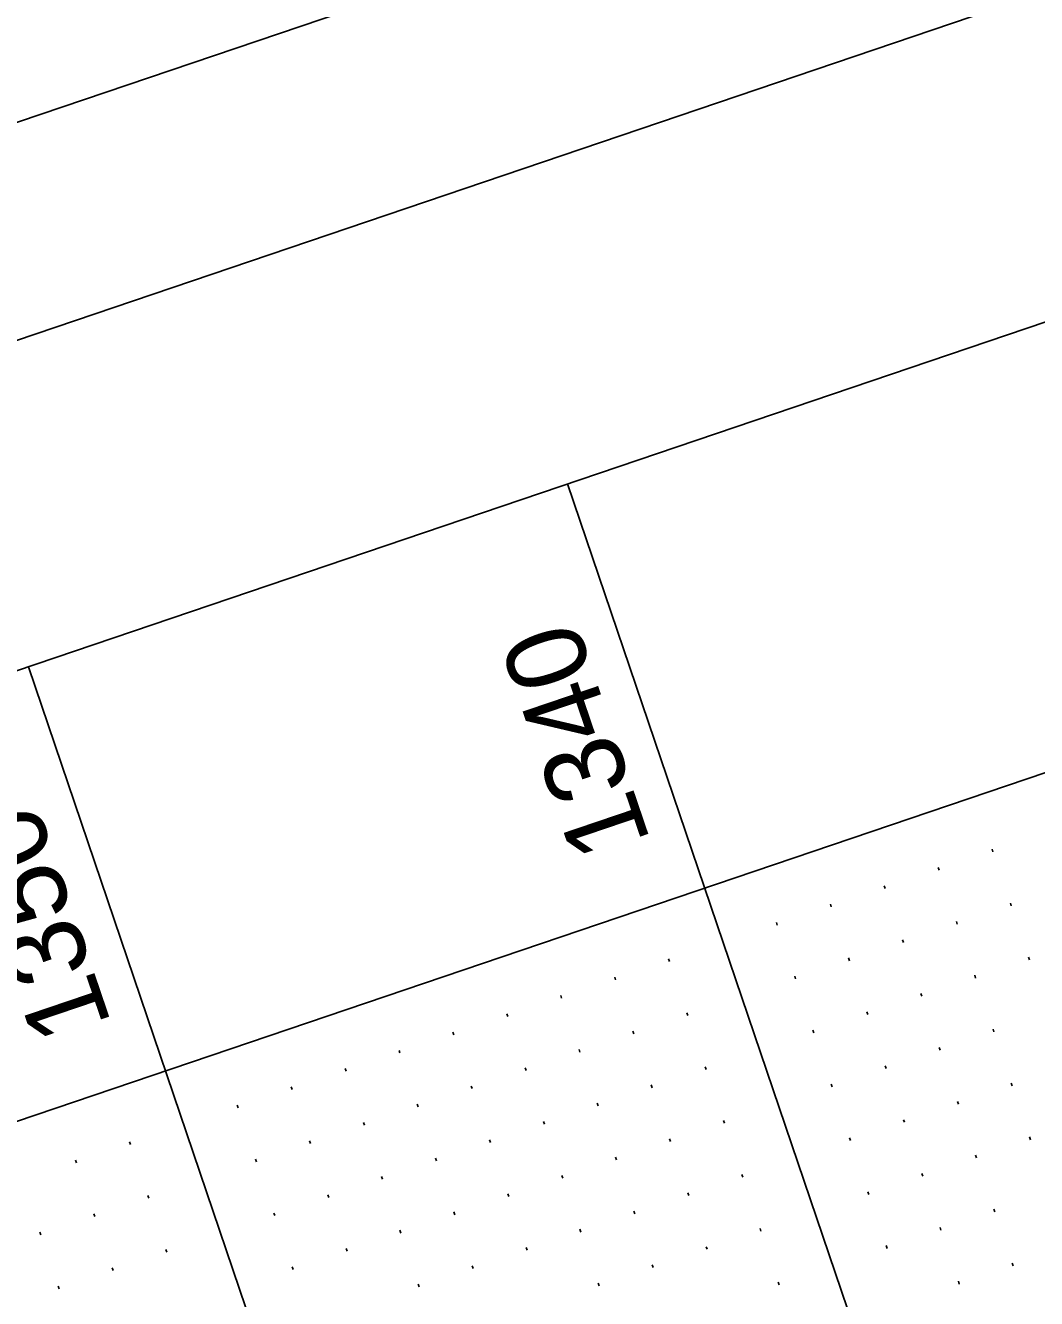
# Model space of a CAD drawing. Extents: x 2150800 to 2152547, y 141860 to 143950.
# Drawn here: x 2151429.1 to 2151517.9, y 143674.4 to 143786.3 of the extents above; entities that cross this region are included whole.
import ezdxf

# ---------------------------------------------------------------- set-up
doc = ezdxf.new("R2010")
doc.units = 0
for name, color, linetype in [('SHT_Plan_Profile_Sheet_Elev_Txt', 7, 'Continuous'), ('SHT_Plot_Shape_Full', 7, 'Continuous'), ('SHT_Plot_Shape_Half', 7, 'Continuous'), ('SHT_Profile_Grid_Major', 7, 'Continuous'), ('SHT_Profile_Grid_Minor', 7, 'Continuous'), ('SHT_Sheet_Border', 7, 'Continuous')]:
    doc.layers.add(name, color=color, linetype=linetype)

msp = doc.modelspace()

# ---------------------------------------------------------------- linework, layer by layer
at = {"layer": 'SHT_Plot_Shape_Full'}
msp.add_lwpolyline([(2151378.63, 141860.13), (2150800.36, 143564.71), (2151936.74, 143950.23), (2152515.02, 142245.65)], close=True, dxfattribs=at)
at = {"layer": 'SHT_Plot_Shape_Half'}
msp.add_lwpolyline([(2151391.39, 141950.92), (2150845.24, 143560.8), (2151886.93, 143914.19), (2152433.08, 142304.31)], close=True, dxfattribs=at)
at = {"layer": 'SHT_Profile_Grid_Major'}
for p, q in [((2151982.71, 142254.48), (2151476.72, 143745.99)), ((2151935.36, 142238.42), (2151429.37, 143729.93))]:
    msp.add_line(p, q, dxfattribs=at)
at = {"layer": 'SHT_Profile_Grid_Minor'}
for p, q in [((2151514.09, 143713.66), (2151514.01, 143713.89)), ((2151509.36, 143712.05), (2151509.28, 143712.29)), ((2151504.62, 143710.44), (2151504.54, 143710.68)), ((2151499.89, 143708.84), (2151499.81, 143709.07)), ((2151515.7, 143708.92), (2151515.62, 143709.16)), ((2151495.15, 143707.23), (2151495.07, 143707.47)), ((2151510.96, 143707.31), (2151510.88, 143707.55)), ((2151506.23, 143705.71), (2151506.15, 143705.94)), ((2151485.68, 143704.02), (2151485.6, 143704.25)), ((2151501.49, 143704.1), (2151501.41, 143704.34)), ((2151517.3, 143704.19), (2151517.22, 143704.42)), ((2151480.95, 143702.41), (2151480.87, 143702.65)), ((2151496.76, 143702.5), (2151496.68, 143702.73)), ((2151512.57, 143702.58), (2151512.49, 143702.82)), ((2151507.83, 143700.97), (2151507.75, 143701.21)), ((2151476.21, 143700.8), (2151476.13, 143701.04)), ((2151471.48, 143699.2), (2151471.4, 143699.44)), ((2151487.29, 143699.28), (2151487.21, 143699.52)), ((2151503.1, 143699.37), (2151503.02, 143699.6)), ((2151466.74, 143697.59), (2151466.66, 143697.83)), ((2151482.55, 143697.68), (2151482.47, 143697.91)), ((2151498.36, 143697.76), (2151498.28, 143698)), ((2151514.18, 143697.84), (2151514.1, 143698.08)), ((2151462.01, 143695.99), (2151461.93, 143696.22)), ((2151477.82, 143696.07), (2151477.74, 143696.31)), ((2151509.44, 143696.24), (2151509.36, 143696.47)), ((2151457.27, 143694.38), (2151457.19, 143694.62)), ((2151473.08, 143694.46), (2151473, 143694.7)), ((2151488.89, 143694.55), (2151488.81, 143694.78)), ((2151504.71, 143694.63), (2151504.63, 143694.87)), ((2151499.97, 143693.03), (2151499.89, 143693.26)), ((2151515.78, 143693.11), (2151515.7, 143693.35)), ((2151452.54, 143692.77), (2151452.46, 143693.01)), ((2151468.35, 143692.86), (2151468.27, 143693.09)), ((2151484.16, 143692.94), (2151484.08, 143693.18)), ((2151447.8, 143691.17), (2151447.72, 143691.4)), ((2151463.61, 143691.25), (2151463.53, 143691.49)), ((2151479.42, 143691.34), (2151479.34, 143691.57)), ((2151511.05, 143691.5), (2151510.97, 143691.74)), ((2151474.69, 143689.73), (2151474.61, 143689.97)), ((2151490.5, 143689.81), (2151490.42, 143690.05)), ((2151506.31, 143689.9), (2151506.23, 143690.13)), ((2151458.88, 143689.64), (2151458.8, 143689.88)), ((2151438.33, 143687.95), (2151438.25, 143688.19)), ((2151454.14, 143688.04), (2151454.06, 143688.28)), ((2151469.95, 143688.12), (2151469.87, 143688.36)), ((2151485.77, 143688.21), (2151485.69, 143688.44)), ((2151501.58, 143688.29), (2151501.5, 143688.53)), ((2151517.39, 143688.37), (2151517.31, 143688.61)), ((2151433.6, 143686.35), (2151433.52, 143686.58)), ((2151449.41, 143686.43), (2151449.33, 143686.67)), ((2151465.22, 143686.52), (2151465.14, 143686.75)), ((2151481.03, 143686.6), (2151480.95, 143686.84)), ((2151512.65, 143686.77), (2151512.57, 143687)), ((2151460.48, 143684.91), (2151460.4, 143685.15)), ((2151476.3, 143684.99), (2151476.22, 143685.23)), ((2151492.11, 143685.08), (2151492.03, 143685.31)), ((2151507.92, 143685.16), (2151507.84, 143685.4)), ((2151439.94, 143683.22), (2151439.86, 143683.46)), ((2151455.75, 143683.3), (2151455.67, 143683.54)), ((2151471.56, 143683.39), (2151471.48, 143683.62)), ((2151487.37, 143683.47), (2151487.29, 143683.71)), ((2151503.18, 143683.56), (2151503.1, 143683.79)), ((2151482.64, 143681.87), (2151482.56, 143682.1)), ((2151514.26, 143682.03), (2151514.18, 143682.27)), ((2151435.2, 143681.61), (2151435.12, 143681.85)), ((2151451.01, 143681.7), (2151450.93, 143681.93)), ((2151466.83, 143681.78), (2151466.75, 143682.02)), ((2151430.47, 143680.01), (2151430.39, 143680.24)), ((2151462.09, 143680.17), (2151462.01, 143680.41)), ((2151477.9, 143680.26), (2151477.82, 143680.5)), ((2151493.71, 143680.34), (2151493.63, 143680.58)), ((2151509.52, 143680.43), (2151509.44, 143680.66)), ((2151441.54, 143678.48), (2151441.46, 143678.72)), ((2151457.36, 143678.57), (2151457.28, 143678.81)), ((2151473.17, 143678.65), (2151473.09, 143678.89)), ((2151488.98, 143678.74), (2151488.9, 143678.97)), ((2151504.79, 143678.82), (2151504.71, 143679.06)), ((2151436.81, 143676.88), (2151436.73, 143677.11)), ((2151452.62, 143676.96), (2151452.54, 143677.2)), ((2151468.43, 143677.05), (2151468.35, 143677.28)), ((2151484.24, 143677.13), (2151484.16, 143677.37)), ((2151515.87, 143677.3), (2151515.79, 143677.53)), ((2151432.08, 143675.27), (2151431.99, 143675.51)), ((2151463.7, 143675.44), (2151463.62, 143675.68)), ((2151479.51, 143675.52), (2151479.43, 143675.76)), ((2151495.32, 143675.61), (2151495.24, 143675.84)), ((2151511.13, 143675.69), (2151511.05, 143675.93))]:
    msp.add_line(p, q, dxfattribs=at)
at = {"layer": 'SHT_Sheet_Border'}
msp.add_line((2151843.89, 143830.95), (2151394.07, 143678.35), dxfattribs=at)
msp.add_lwpolyline([(2151383.74, 142051.28), (2150877.75, 143542.79), (2151872.09, 143880.12), (2152378.08, 142388.61)], close=True, dxfattribs=at)

# ---------------------------------------------------------------- texts
at = {"layer": 'SHT_Plan_Profile_Sheet_Elev_Txt'}
for s, p in [('1340', (2151484.05, 143714.57)), ('1350', (2151436.7, 143698.51))]:
    msp.add_text(s, height=7, rotation=108.7393, dxfattribs=at).set_placement(p)

doc.saveas('drawing.dxf')
